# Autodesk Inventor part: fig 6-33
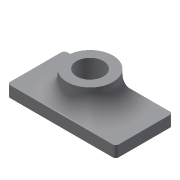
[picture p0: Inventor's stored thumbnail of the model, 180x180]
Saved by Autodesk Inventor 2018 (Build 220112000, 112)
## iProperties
Created: 2004-05
Part Number: fig 6-33
Document SubType Name: Modeling
Designer: CADCIM Technologies
Manufacturer: Standard
Standards Organization: Custom
Density: 1 g/cm^3
Material: Generic
Appearance: Default
Author: CADCIM Technologies
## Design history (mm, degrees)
sketch "Sketch1"
  geometry: L1 (-39.276, -18.692)-(33.721, -18.692); L2 (33.721, -18.692)-(33.721, 19.728); L3 (33.721, 19.728)-(-39.276, 19.728); L4 (-39.276, 19.728)-(-39.276, -18.692)
  constraints: 8 end point, 2 parallel, 1 horizontal, 1 perpendicular
extrude "Extrusion1" new body sketch "Sketch1" distance "d0" = 7.5; taper "d1" = 0 deg
fillet "Fillet1" dims "d2" = 2
sketch "Sketch2"
  geometry: C1 r 15.456 at (-2.778, 0.518)
  constraints: 1 centre point
extrude "Extrusion2" join sketch "Sketch2" distance "d3" = 17.25; taper "d4" = 0 deg
hole "Hole1" diameter "d8" = 18; stored, may be unused: countersink angle "d12" = 90 deg, drill point angle "d14" = 118 deg; dims "d6" = 10, "d7" = 10, "d9" = 6, "d10" = 4, "d11" = 2, "d13" = 8
fillet "Fillet2" dims "d5" = 14
body "Solid1"
